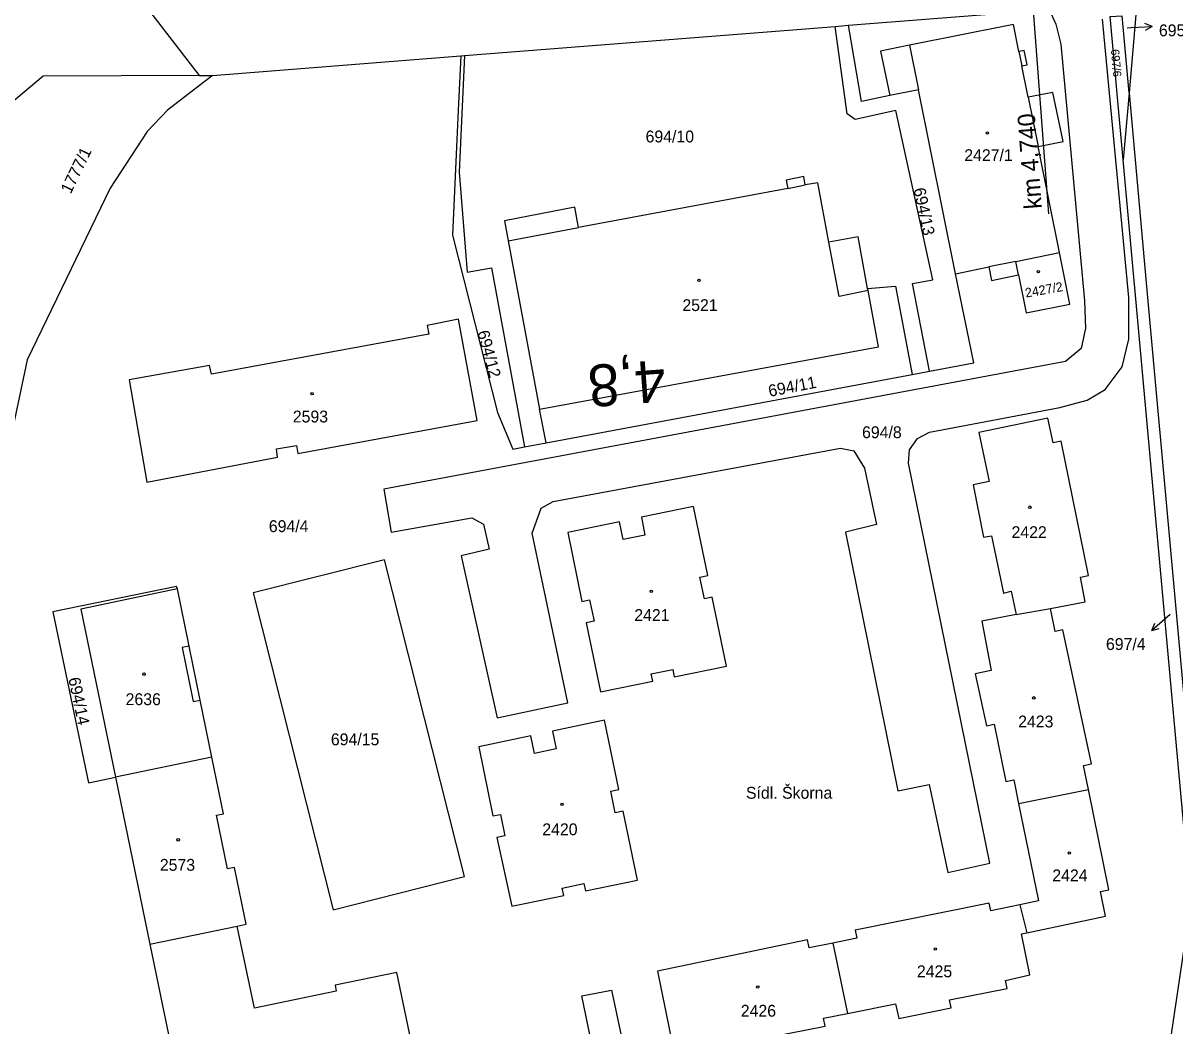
# Model space of a CAD drawing. Extents: x -779330 to -774454, y -1144748 to -1142831.
# Drawn here: x -775094 to -774928.8, y -1144606.1 to -1144462.2 of the extents above; entities that cross this region are included whole.
import ezdxf

# ---------------------------------------------------------------- set-up
doc = ezdxf.new("R2010")
doc.units = 0
for name, color, linetype in [('Hranice parcel', 7, 'Continuous'), ('legenda - Vrstva 7', 7, 'Continuous'), ('Parcelní čísla', 7, 'Continuous'), ('Pop  PČ popisy', 7, 'Continuous'), ('Vnitřní kresba', 7, 'Continuous'), ('Vrstva 7', 7, 'Continuous'), ('Značky budov', 7, 'Continuous')]:
    doc.layers.add(name, color=color, linetype=linetype)

msp = doc.modelspace()

# ---------------------------------------------------------------- linework, layer by layer
at = {"layer": 'Hranice parcel'}
for p, q in [((-775076.86, -1144459.23), (-775068.75, -1144469.74)), ((-774975.61, -1144462.52), (-774946.81, -1144460.25)), ((-774935.34, -1144472.21), (-774936.34, -1144461.16)), ((-774934.36, -1144461.03), (-774935.34, -1144472.21)), ((-774977.53, -1144462.71), (-774975.61, -1144462.52)), ((-775066.86, -1144469.73), (-775031.24, -1144466.92)), ((-775031.24, -1144466.92), (-775030.68, -1144466.87)), ((-775068.75, -1144469.74), (-775066.86, -1144469.73)), ((-774935.34, -1144472.21), (-774936.18, -1144481.83)), ((-774935.34, -1144472.21), (-774932.82, -1144500)), ((-774926.48, -1144588.49), (-774936.18, -1144481.83)), ((-774932.82, -1144500), (-774925.31, -1144582.51)), ((-775018.98, -1144522.44), (-774966.48, -1144512.63)), ((-774966.48, -1144512.63), (-774963.98, -1144512.17)), ((-775018.98, -1144522.44), (-775019.94, -1144517.62)), ((-775022.07, -1144523.02), (-775018.98, -1144522.44)), ((-774951.55, -1144547.07), (-774946.62, -1144546.23)), ((-775066.94, -1144567.53), (-775080.75, -1144570.41)), ((-775080.75, -1144570.41), (-775075.83, -1144594.37)), ((-774951.18, -1144574.18), (-774941.18, -1144572.17)), ((-774951, -1144588.72), (-774950.02, -1144592.74)), ((-775075.83, -1144594.37), (-775063.33, -1144591.78)), ((-774977.82, -1144594.22), (-774975.76, -1144604.34))]:
    msp.add_line(p, q, dxfattribs=at)
for points in [[(-774946.81, -1144460.25), (-774945.83, -1144462.36), (-774945.13, -1144465.25), (-774941.71, -1144502.06), (-774941.57, -1144505.98), (-774942.23, -1144508.88), (-774944.46, -1144510.75), (-775042.26, -1144529.08), (-775041.21, -1144535.25), (-775029.64, -1144533.2), (-775027.98, -1144534.13), (-775027.15, -1144537.72), (-775031.16, -1144538.67), (-775025.99, -1144561.88), (-775015.89, -1144559.74), (-775021, -1144535.42), (-775019.67, -1144531.82), (-775017.95, -1144530.88), (-774976.76, -1144523.19), (-774974.85, -1144523.59), (-774973.29, -1144526.08), (-774971.56, -1144534.16), (-774976.03, -1144535.26), (-774968.53, -1144572.4), (-774964.04, -1144571.46), (-774961.35, -1144584.12), (-774955.31, -1144582.77), (-774966.99, -1144525.35), (-774966.86, -1144523.45), (-774965.7, -1144521.8), (-774963.95, -1144520.9), (-774945.27, -1144517.35), (-774941.33, -1144516.3), (-774938.75, -1144514.81), (-774936.31, -1144511.55), (-774935.35, -1144507.58), (-774935.39, -1144501.57), (-774939.15, -1144461.66)], [(-774945.34, -1144495.11), (-774948.39, -1144479.92), (-774944.8, -1144479.21), (-774946.27, -1144472.15), (-774949.81, -1144472.84), (-774950.71, -1144468.34), (-774949.97, -1144468.19), (-774950.38, -1144466.13), (-774951.13, -1144466.27), (-774951.9, -1144462.39), (-774966.83, -1144465.38), (-774970.98, -1144466.22), (-774969.64, -1144472.62)], [(-774936.18, -1144481.83), (-774938.05, -1144461.28), (-774936.34, -1144461.16)], [(-775030.68, -1144466.87), (-774981.78, -1144463.01), (-774977.53, -1144462.71)], [(-774963.98, -1144512.17), (-774966.4, -1144499.6), (-774963.5, -1144499.07), (-774968.82, -1144474.76), (-774974.62, -1144476.02), (-774975.77, -1144475.24), (-774977.53, -1144462.71)], [(-774969.64, -1144472.62), (-774973.74, -1144473.44), (-774974.84, -1144467), (-774975.61, -1144462.52)], [(-775031.24, -1144466.92), (-775031.6, -1144474.7), (-775032.41, -1144492.66), (-775025.96, -1144518.08), (-775023.75, -1144523.35), (-775022.07, -1144523.02)], [(-775030.68, -1144466.87), (-775031.45, -1144483.59), (-775030.29, -1144497.96), (-775026.8, -1144497.32), (-775022.07, -1144523.02)], [(-775066.86, -1144469.73), (-775073.3, -1144474.69), (-775076.25, -1144477.78), (-775081.56, -1144485.89), (-775093.44, -1144510.53), (-775102.62, -1144553.8), (-775111.39, -1144585.09), (-775117.05, -1144604.72), (-775118.64, -1144626.24)], [(-775068.75, -1144469.74), (-775091.13, -1144469.84), (-775103.59, -1144480.25)], [(-774960.24, -1144498.17), (-774965.54, -1144471.8), (-774969.64, -1144472.62)], [(-774972.85, -1144500.27), (-774974.21, -1144492.89), (-774978.42, -1144493.64), (-774980.01, -1144485.11), (-774981.79, -1144485.44), (-774982.01, -1144484.24), (-774984.54, -1144484.75), (-774984.32, -1144485.92), (-775014.34, -1144491.54), (-775014.88, -1144488.6), (-775024.95, -1144490.57), (-775024.42, -1144493.43), (-775019.94, -1144517.62)], [(-774951.2, -1144498.34), (-774951.6, -1144496.4), (-774945.34, -1144495.11)], [(-774951.2, -1144498.34), (-774950.1, -1144503.77), (-774943.85, -1144502.54), (-774945.34, -1144495.11)], [(-774963.98, -1144512.17), (-774957.59, -1144510.97), (-774960.24, -1144498.17)], [(-774960.24, -1144498.17), (-774955.46, -1144497.19), (-774955.06, -1144499.13), (-774951.2, -1144498.34)], [(-775019.94, -1144517.62), (-774971.3, -1144508.68), (-774972.79, -1144500.6), (-774972.85, -1144500.27)], [(-774972.85, -1144500.27), (-774968.87, -1144499.96), (-774966.48, -1144512.63)], [(-775057.68, -1144523.31), (-775054.81, -1144522.81), (-775054.6, -1144523.96), (-775028.86, -1144519.23), (-775031.57, -1144504.68), (-775036.03, -1144505.59), (-775035.8, -1144506.85), (-775066.98, -1144512.61), (-775067.28, -1144511.33), (-775078.83, -1144513.41), (-775076.29, -1144528.08), (-775057.53, -1144524.49), (-775057.68, -1144523.31)], [(-774946.62, -1144546.23), (-774941.62, -1144545.26), (-774942.3, -1144541.71), (-774941.17, -1144541.48), (-774945.1, -1144522.18), (-774946.23, -1144522.42), (-774947, -1144518.92), (-774956.89, -1144520.97), (-774955.41, -1144527.99), (-774957.72, -1144528.45), (-774956.22, -1144536), (-774955.08, -1144535.77), (-774953.37, -1144543.99), (-774952.24, -1144543.75), (-774951.55, -1144547.07)], [(-775015.89, -1144535.3), (-775013.86, -1144545.2), (-775012.74, -1144544.97), (-775012.1, -1144548.05), (-775013.23, -1144548.28), (-775011.19, -1144558.19), (-775003.69, -1144556.66), (-775003.91, -1144555.58), (-775000.82, -1144554.95), (-775000.6, -1144556.03), (-774993.08, -1144554.5), (-774995.15, -1144544.6), (-774996.28, -1144544.83), (-774996.91, -1144541.74), (-774995.79, -1144541.5), (-774997.84, -1144531.6), (-775005.32, -1144533.13), (-775004.8, -1144535.68), (-775007.91, -1144536.32), (-775008.43, -1144533.77), (-775015.89, -1144535.3)], [(-775061, -1144543.96), (-775049.56, -1144589.46), (-775030.71, -1144584.69), (-775042.15, -1144539.22), (-775061, -1144543.96)], [(-775071.88, -1144543.41), (-775072, -1144543.05), (-775089.75, -1144546.7), (-775084.65, -1144571.23), (-775080.75, -1144570.41)], [(-775071.88, -1144543.41), (-775085.74, -1144546.29), (-775080.75, -1144570.41)], [(-775066.94, -1144567.53), (-775068.61, -1144559.37), (-775070.2, -1144551.61), (-775071.88, -1144543.41)], [(-774941.18, -1144572.17), (-774941.87, -1144568.75), (-774940.75, -1144568.51), (-774944.82, -1144549.27), (-774945.94, -1144549.5), (-774946.62, -1144546.23)], [(-774951.55, -1144547.07), (-774956.48, -1144548.05), (-774955.12, -1144555.1), (-774957.41, -1144555.59), (-774955.81, -1144563.06), (-774954.68, -1144562.82), (-774953, -1144571.03), (-774951.87, -1144570.8), (-774951.18, -1144574.18)], [(-775025.53, -1144575.76), (-775024.92, -1144578.83), (-775026.04, -1144579.07), (-775023.9, -1144588.95), (-775016.44, -1144587.4), (-775016.66, -1144586.34), (-775013.55, -1144585.69), (-775013.33, -1144586.75), (-775005.88, -1144585.19), (-775007.93, -1144575.29), (-775009.06, -1144575.52), (-775009.7, -1144572.42), (-775008.57, -1144572.18), (-775010.63, -1144562.26), (-775018.09, -1144563.83), (-775017.55, -1144566.37), (-775020.64, -1144567.02), (-775021.17, -1144564.48), (-775028.63, -1144566.06), (-775026.65, -1144575.98), (-775025.53, -1144575.76)], [(-775063.33, -1144591.78), (-775062.01, -1144591.5), (-775063.68, -1144583.36), (-775064.72, -1144583.57), (-775066.3, -1144575.87), (-775065.26, -1144575.66), (-775066.94, -1144567.53)], [(-774950.02, -1144592.74), (-774938.71, -1144590.35), (-774939.45, -1144586.84), (-774938.26, -1144586.58), (-774941.18, -1144572.17)], [(-774951.18, -1144574.18), (-774948.33, -1144588.17), (-774951, -1144588.72)], [(-774951, -1144588.72), (-774955.16, -1144589.62), (-774955.39, -1144588.5), (-774974.64, -1144592.38), (-774974.41, -1144593.52), (-774977.82, -1144594.22)], [(-775075.83, -1144594.37), (-775071.62, -1144614.78), (-775072.06, -1144614.87), (-775070.99, -1144620.02), (-775065.84, -1144618.96), (-775065.93, -1144618.52), (-775042.01, -1144613.59), (-775041.52, -1144615.98), (-775036.95, -1144615.04), (-775037.44, -1144612.65), (-775040.4, -1144598.45), (-775049.27, -1144600.27), (-775049.09, -1144601.14), (-775060.81, -1144603.59), (-775063.33, -1144591.78)], [(-774975.76, -1144604.34), (-774968.83, -1144602.94), (-774968.37, -1144605.03), (-774960.85, -1144603.5), (-774961.08, -1144602.37), (-774952.85, -1144600.73), (-774953.08, -1144599.6), (-774949.58, -1144598.79), (-774950.76, -1144592.9), (-774950.02, -1144592.74)], [(-774977.82, -1144594.22), (-774981.23, -1144594.91), (-774981.46, -1144593.78), (-775003.02, -1144598.27), (-775000.75, -1144609.29), (-774997.23, -1144608.54), (-774996.99, -1144609.71), (-774978.94, -1144606.14), (-774979.16, -1144605.01), (-774975.76, -1144604.34)], [(-775118.64, -1144626.24), (-775117.63, -1144626.76), (-775114.02, -1144628.64), (-775111.15, -1144629.56), (-775108.25, -1144630.03), (-775072.11, -1144632.49), (-775068.93, -1144632.43), (-775065.26, -1144631.94), (-775016.08, -1144622.26), (-775013.91, -1144621.39), (-775011.81, -1144619.33), (-775011.07, -1144617.04), (-775011.04, -1144615.41), (-775013.87, -1144601.8), (-775009.6, -1144600.96), (-775006.67, -1144614.66), (-775004.63, -1144616.87), (-775002.85, -1144617.85), (-774999.95, -1144618.02), (-774954.26, -1144608.09), (-774953.35, -1144612.05)]]:
    msp.add_lwpolyline(points, dxfattribs=at)
at = {"layer": 'legenda - Vrstva 7'}
msp.add_lwpolyline([(-774851.19, -1144648.48), (-774933.55, -1144636.29), (-774925.58, -1144582.47), (-774843.23, -1144594.66)], close=True, dxfattribs=at)
at = {"layer": 'Pop  PČ popisy'}
for p, q in [((-774932.04, -1144462.7), (-774933.07, -1144462.26)), ((-774935.63, -1144462.89), (-774935.04, -1144462.86)), ((-774935.04, -1144462.86), (-774932.04, -1144462.7)), ((-774932.04, -1144462.7), (-774933.02, -1144463.26)), ((-774929.82, -1144547.39), (-774932.08, -1144549.36)), ((-774932.08, -1144549.36), (-774931.66, -1144548.32)), ((-774929.46, -1144547.08), (-774929.82, -1144547.39)), ((-774932.08, -1144549.36), (-774931, -1144549.08))]:
    msp.add_line(p, q, dxfattribs=at)
at = {"layer": 'Vnitřní kresba'}
for p, q in [((-774966.83, -1144465.38), (-774965.54, -1144471.8)), ((-774951.13, -1144466.27), (-774950.71, -1144468.34)), ((-774949.81, -1144472.84), (-774948.39, -1144479.92)), ((-774984.32, -1144485.92), (-774981.79, -1144485.44)), ((-775024.42, -1144493.43), (-775014.34, -1144491.54)), ((-774976.95, -1144501.46), (-774978.42, -1144493.64)), ((-774951.6, -1144496.4), (-774955.46, -1144497.19)), ((-774972.79, -1144500.6), (-774976.95, -1144501.46)), ((-775070.2, -1144551.61), (-775071.22, -1144551.82)), ((-775071.22, -1144551.82), (-775069.63, -1144559.58)), ((-775069.63, -1144559.58), (-775068.61, -1144559.37))]:
    msp.add_line(p, q, dxfattribs=at)
at = {"layer": 'Vrstva 7'}
msp.add_line((-774950.33, -1144444.39), (-774946.91, -1144489.58), dxfattribs=at)
at = {"layer": 'Značky budov'}
for centre in [(-774955.66, -1144477.97), (-774948.37, -1144497.89), (-774997.06, -1144499.11), (-775052.56, -1144515.37), (-774949.57, -1144531.68), (-775003.89, -1144543.75), (-775076.69, -1144555.64), (-774949, -1144559.04), (-775016.71, -1144574.32), (-775071.78, -1144579.41), (-774943.91, -1144581.3), (-774963.15, -1144595.07), (-774988.61, -1144600.54)]:
    msp.add_circle(centre, 0.175, dxfattribs=at)

# ---------------------------------------------------------------- texts
at = {"layer": 'Parcelní čísla'}
for s, p in [('695/4', (-774931.05, -1144464.1)), ('694/10', (-775004.71, -1144479.33)), ('2427/1', (-774958.98, -1144482.01)), ('2521', (-774999.43, -1144503.53)), ('2593', (-775055.33, -1144519.52)), ('694/8', (-774973.65, -1144521.77)), ('694/4', (-775058.77, -1144535.25)), ('2422', (-774952.2, -1144536.11)), ('2421', (-775006.33, -1144548)), ('697/4', (-774938.65, -1144552.17)), ('2636', (-775079.32, -1144560.08)), ('2423', (-774951.25, -1144563.28)), ('694/15', (-775049.87, -1144565.84)), ('2420', (-775019.53, -1144578.75)), ('2573', (-775074.41, -1144583.85)), ('2424', (-774946.35, -1144585.36)), ('2425', (-774965.78, -1144599.13)), ('2426', (-774991.05, -1144604.79))]:
    msp.add_text(s, height=1.7, dxfattribs=at).set_placement(p)
for s, height, rotation, p in [('697/6', 1.19, 275, (-774937.95, -1144466.01)), ('1777/1', 1.7, 64, (-775087.2, -1144486.81)), ('694/13', 1.7, 282, (-774966.28, -1144486.02)), ('2427/2', 1.337, 10, (-774950.13, -1144501.6)), ('694/12', 1.7, 285, (-775028.87, -1144506.54)), ('694/11', 1.7, 11, (-774986.92, -1144515.85)), ('694/14', 1.7, 282, (-775087.56, -1144556.27))]:
    msp.add_text(s, height=height, rotation=rotation, dxfattribs=at).set_placement(p)
at = {"layer": 'Pop  PČ popisy'}
msp.add_text('Sídl. Škorna', height=1.7, dxfattribs=at).set_placement((-774990.31, -1144573.51))
at = {"layer": 'Vrstva 7'}
for s, height, rotation, p in [('km 4,740', 2.5, 94.3247, (-774947.84, -1144488.8)), ('4,8', 6, 184.305, (-775002.05, -1144510.51))]:
    msp.add_text(s, height=height, rotation=rotation, dxfattribs=at).set_placement(p)

doc.saveas('drawing.dxf')
